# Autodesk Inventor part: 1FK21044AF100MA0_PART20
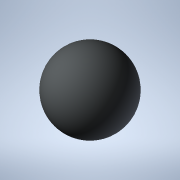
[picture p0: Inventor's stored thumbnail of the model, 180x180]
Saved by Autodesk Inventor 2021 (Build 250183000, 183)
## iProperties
Created: 2025-04
Part Number: 1FK21044AF100MA0_PART20
Material: Generic
Catalog Web Link: www.3dfindit.com
Description: -Servo synchronous motor
Document SubType Name: Modeling
Designer: psAdmin
Mass: 0.137258 g
Surface Area: 1.2868 cm^2
Volume: 0.137258 cm^3
Density: 1 g/cm^3
Appearance: PSOLRGB-212-217-219
Category: PARTsolutions
Title: 1FK21044AF100MA0_PART20
Author: Cadenas PARTsolutions
Comments: Servo synchronous motor
Sending System: PARTsolutions
Preprocessor: ST-DEVELOPER v19.3
PSOL_IDENT_0: {$CADENAS_DATA/23d-libs/siemens_ag/_cat_/ec/e4/1fk21044af100ma0.prj},216 {VTYP=3D},{NB=1FK21044AF100
PSOL_IDENT_1: MA0_PART20},{LINA=1FK21044AF100MA0_PART20},{NN=1FK21044AF100MA0_PART20},{NOPRJ=TRUE},{DATE=19.08.202
PSOL_IDENT_2: 5 14:01:05},{GEOMDATE=30.07.2025 02:01:01},{VERSION=},{LINEID=10},{WBVAR=},{WBNUMERIC=}  {NB=1FK2104
PSOL_IDENT_3: 4AF100MA0_PART20},{LINA=1FK21044AF100MA0_PART20},{KT=DUMMY},{PREVIEW=../../../_pool_/cb/72/p_d211_xx
PSOL_IDENT_4: _00434j.png},{DESCSHORT=SIMOTICS S-1FK2 HD, SINAMICS S210 3AC 400V-480V, 1.27 Nm, 3000 rpm},{DESCLON
PSOL_IDENT_5: G=SIMOTICS S-1FK2 HD servo motor M0=1.27 Nm; PN = 0.4 kW at nN=3000 rpm (380-480 V); PN = 0.2 kW at
PSOL_IDENT_6: nN=1500 rpm (200-240 V); with holding brake; degree of protection IP64; cylindrical shaft D19x40mm;
PSOL_IDENT_7: absolute encoder 22-bit + 12-bit multiturn (encoder AM22DQC); with OCC interface; plug size M17, rot
PSOL_IDENT_8: atable; SIMOTICS S-1FK2 servomotorfor a wide range of uses in industrial environments. SIMOTICS S‑1F
PSOL_IDENT_9: K2 servomotors are compact synchronous motors with a high dynamic performance that set themselves ap
PSOL_IDENT_10: art as a result of their high power density, degree of protection and overload capability. The motor
PSOL_IDENT_11: s are available in two variants: as High Dynamic variant (highest dynamic performance as a result of
PSOL_IDENT_12: the low intrinsic moment of inertia for applications demanding a high dynamic performance with low
PSOL_IDENT_13: moved masses) - and as Compact variant (precise and stable closed-loop control for medium up to larg
PSOL_IDENT_14: e moved masses as a result of a medium intrinsic moment of inertia). SIMOTICSS‑1FK2 servomotors full
PSOL_IDENT_15: y exploit their strengths in a system with the SINAMICSS210 frequency converter and simple connectio
PSOL_IDENT_16: n using the one cable connection (OCC). Advantages include the short control and positioning times,
PSOL_IDENT_17: fast and precise correction of disturbing quantities as well as stable control with a high dynamic p
PSOL_IDENT_18: erformance. The servo motors can be configured to address a wide range of requirements. For example
PSOL_IDENT_19: with and without holding brake, IP64 or IP65 degree of protection, singleturn or multiturn absolute
PSOL_IDENT_20: encoders - to name just a few. Further, the servomotors are available in different shaft heights ext
PSOL_IDENT_21: ending from 20 to 100. A shaft sealing ring is available to achieve an IP65 degree of protection and
PSOL_IDENT_22: for subsequent mounting at the motor or as spare part. SIMOTICS - the optimum motor for each and ev
PSOL_IDENT_23: ery motion control application.},{INTNO=195125043275},{SUPPLIERALTNO=1FK2104-4AF10-0MA0},{MANUID=1FK
PSOL_IDENT_24: 21044AF100MA0},{MANUNAME=Siemens},{MANUTYPEDESC=Synchronous motor 1FK2-HD 1.27 NM},{AAU732=SIMOTICS}
PSOL_IDENT_25: ,{AAO057=S-1FK2},{AAU734=SIMOTICS S-1FK2 HD servo motor M0=1.27 Nm; PN = 0.4 kW at nN=3000 rpm (380-
PSOL_IDENT_26: 480 V); PN = 0.2 kW at nN=1500 rpm (200-240 V); with holding brake; degree of protection IP64; cylin
PSOL_IDENT_27: drical shaft D19x40mm; absolute encoder 22-bit + 12-bit multiturn (encoder AM22DQC); with OCC interf
PSOL_IDENT_28: ace; plug size M17, rotatable;},{AAW338=Synchronous motor 1FK2-HD 1.27 NM},{AAO742=SIMOTICS},{AAO663=
PSOL_IDENT_29: 4042948694015},{NOCUPEROU=1},{PRICEQUANTITY=1},{QUANTITYMIN=1},{QUANTITYINT=1},{CTN=85015100},{COO=D
PSOL_IDENT_30: E},{AAO676=1FK2104-4AF10-0MA0},{AAO677=Siemens AG},{ORDERUNIT=C62},{CONTENTUNIT=C62}
NB: 1FK21044AF100MA0_PART20
NT: Servo synchronous motor
NBSYN: $MANUID._PART20
LINA: 1FK21044AF100MA0_PART20
CATALOG: SIEMENS
PREVIEW: ../../../_pool_/cb/72/p_d211_xx_00434j.png
DESCSHORT: SIMOTICS S-1FK2 HD, SINAMICS S210 3AC 400V-480V, 1.27 Nm, 3000 rpm
DESCLONG: SIMOTICS S-1FK2 HD servo motor M0=1.27 Nm; PN = 0.4 kW at nN=3000 rpm (380-480 V); PN = 0.2 kW at nN=1500 rpm (200-240 V); with holding brake; degree of protect
INTNO: 195125043275
SUPPLIERALTNO: 1FK2104-4AF10-0MA0
MANUID: 1FK21044AF100MA0
MANUNAME: Siemens
MANUTYPEDESC: Synchronous motor 1FK2-HD 1.27 NM
AAU732: SIMOTICS
AAO057: S-1FK2
AAU734: SIMOTICS S-1FK2 HD servo motor M0=1.27 Nm; PN = 0.4 kW at nN=3000 rpm (380-480 V); PN = 0.2 kW at nN=1500 rpm (200-240 V); with holding brake; degree of protect
AAW338: Synchronous motor 1FK2-HD 1.27 NM
AAO742: SIMOTICS
AAO663: 4042948694015.0
NOCUPEROU: 1
PRICEQUANTITY: 1
QUANTITYMIN: 1
QUANTITYINT: 1
CTN: 85015100
COO: DE
ARTICLENO: 1FK21044AF100MA0_PART20
BOMINFO: 1FK21044AF100MA0_PART20
CREATOR: CADENAS GmbH
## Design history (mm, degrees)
feature "2025_04_17_15_33_01_0673"
body "Solid1"
